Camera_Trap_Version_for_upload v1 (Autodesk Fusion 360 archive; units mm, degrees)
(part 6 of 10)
sketch "Sketch3" plane through (-24, 0, 0) normal (-1, 0, 0) x axis (0, -1, 0)
  line L1 (-33, 30) -> (-53, 30)
  line L2 (-2.8201, 30) -> (-33, 30)
  curve K1 (35.395, 253.2053) -> (39.3474, 235.851)
  line L3 (35.395, 254.9773) -> (35.395, 253.2053)
  line L4 (-53.3744, 254.9773) -> (35.395, 254.9773)
  line L5 (-53.3744, 30) -> (-53.3744, 254.9773)
  line L6 (-53, 30) -> (-53.3744, 30)
  line L7 (-35, 194) -> (-35, 213)
  line L8 (-42, 194) -> (-35, 194)
  line L9 (-42, 213) -> (-42, 194)
  line L10 (-35, 213) -> (-42, 213)
  line L11 (-46.1387, 104.755) -> (-18.6307, 104.755)
  line L12 (-49.1387, 175.7967) -> (-49.1387, 107.755)
  line L13 (-18.6307, 178.7967) -> (-46.1387, 178.7967)
  line L14 (-15.6307, 107.755) -> (-15.6307, 175.7967)
  curve K2 (-13.4543, 92.4987) -> (-13.7844, 52.0839)
  curve K3 (-13.7844, 52.0839) -> (10.3481, 52.6282)
  line L15 (23.9949, 221.9266) -> (23.9949, 191.9266)
  line L16 (-16.0051, 231.9266) -> (13.9949, 231.9266)
  line L17 (-26.0051, 191.9266) -> (-26.0051, 221.9266)
  line L18 (13.9949, 181.9266) -> (-16.0051, 181.9266)
  line L19 (9.6256, 120.7716) -> (-33.3744, 120.7716)
  line L20 (17.6256, 146.7716) -> (17.6256, 128.7716)
  line L21 (-33.3744, 154.7716) -> (9.6256, 154.7716)
  line L22 (-41.3744, 128.7716) -> (-41.3744, 146.7716)
  line L23 (35.0206, 254.9769) -> (-53.3744, 254.9769)
  curve K4 (35.0206, 254.9769) -> (38.973, 237.6226)
  line L24 (-3.1945, 31.7716) -> (-33.3744, 31.7716)
  line L25 (-33.3744, 31.7716) -> (-53.3744, 31.7716)
  line L26 (-53.3744, 31.7716) -> (-53.3744, 254.9769)
  curve K5 (21.1288, 76.5054) -> (12.4903, 90.2086)
  curve K6 (12.4903, 90.2086) -> (-13.4543, 92.4987)
  arc A1 centre (-2.8201, 80) radius 50 clockwise from (39.6517, 106.3845) to (-2.8201, 30)
  arc A2 centre (82.1236, 132.769) radius 50 clockwise from (39.6517, 106.3845) to (32.1399, 134.0465)
  arc A3 centre (1.7685, 134.8228) radius 30.3814 clockwise from (31.815, 139.3208) to (32.1399, 134.0465)
  arc A4 centre (81.264, 146.7234) radius 50 clockwise from (31.815, 139.3208) to (40.632, 175.8617)
  arc A5 centre (0, 205) radius 50 clockwise from (39.3474, 235.851) to (40.632, 175.8617)
  arc A6 centre (-46.1387, 107.755) radius 3 clockwise from (-46.1387, 104.755) to (-49.1387, 107.755)
  arc A7 centre (-46.1387, 175.7967) radius 3 clockwise from (-49.1387, 175.7967) to (-46.1387, 178.7967)
  arc A8 centre (-18.6307, 175.7967) radius 3 clockwise from (-18.6307, 178.7967) to (-15.6307, 175.7967)
  arc A9 centre (-18.6307, 107.755) radius 3 clockwise from (-15.6307, 107.755) to (-18.6307, 104.755)
  arc A10 centre (-1.0051, 72.1266) radius 22.5629 clockwise from (21.1288, 76.5054) to (10.3481, 52.6282)
  arc A11 centre (13.9949, 221.9266) radius 10 clockwise from (13.9949, 231.9266) to (23.9949, 221.9266)
  arc A12 centre (-16.0051, 221.9266) radius 10 clockwise from (-26.0051, 221.9266) to (-16.0051, 231.9266)
  arc A13 centre (-16.0051, 191.9266) radius 10 clockwise from (-16.0051, 181.9266) to (-26.0051, 191.9266)
  arc A14 centre (13.9949, 191.9266) radius 10 clockwise from (23.9949, 191.9266) to (13.9949, 181.9266)
  arc A15 centre (-33.3744, 128.7716) radius 8 clockwise from (-33.3744, 120.7716) to (-41.3744, 128.7716)
  arc A16 centre (9.6256, 128.7716) radius 8 clockwise from (17.6256, 128.7716) to (9.6256, 120.7716)
  arc A17 centre (9.6256, 146.7716) radius 8 clockwise from (9.6256, 154.7716) to (17.6256, 146.7716)
  arc A18 centre (-33.3744, 146.7716) radius 8 clockwise from (-41.3744, 146.7716) to (-33.3744, 154.7716)
  arc A19 centre (38.1035, 198.1502) radius 5.767 clockwise from (41.4518, 193.4548) to (34.7552, 193.4548)
  arc A20 centre (38.1035, 88.1502) radius 5.767 clockwise from (41.4518, 83.4548) to (34.7552, 83.4548)
  arc A21 centre (-0.3744, 206.7716) radius 50 clockwise from (38.973, 237.6226) to (40.2576, 177.6333)
  arc A22 centre (80.8896, 148.495) radius 50 clockwise from (31.4406, 141.0924) to (40.2576, 177.6333)
  arc A23 centre (1.3941, 136.5944) radius 30.3814 clockwise from (31.4406, 141.0924) to (31.7655, 135.8181)
  arc A24 centre (81.7492, 134.5406) radius 50 clockwise from (39.2774, 108.1561) to (31.7655, 135.8181)
  arc A25 centre (-3.1945, 81.7716) radius 50 clockwise from (39.2774, 108.1561) to (-3.1945, 31.7716)
sketch "Sketch1" plane through (0, 60, 0) normal (0, 1, 0) x axis (-1, 0, 0)
  line L1 (-132, 253.2053) -> (24, 253.2053)
  line L2 (-132, 28) -> (-132, 253.2053)
  line L3 (24, 28) -> (-132, 28)
  line L4 (24, 253.2053) -> (24, 28)
  line L5 (-54, 222.0559) -> (-54, 253.2053)
  circle C1 centre (-110, 230) radius 2.5
  circle C2 centre (-110, 50) radius 2.5
  circle C3 centre (2, 50) radius 2.5
  circle C4 centre (2, 230) radius 2.5
  point P6 (-54, 253.2053)
  midpoint L1 P6
  perpendicular L1 L5
  symmetric L5 C1 C4
  symmetric L5 C2 C3
  dimension "d1270" diameter C1 = 5
  dimension "d1271" diameter C2 = 5
extrude "Extrude1" cut sketch "Sketch1" profile of C1 C2 C3 C4 to an object
combine "Combine2"
sketch "Sketch2" plane through (-24, 0, 0) normal (-1, 0, 0) x axis (0, -1, 0)
  line L1 (-46.1387, 104.755) -> (-18.6307, 104.755)
  line L2 (-49.1387, 175.7967) -> (-49.1387, 107.755)
  line L3 (-18.6307, 178.7967) -> (-46.1387, 178.7967)
  line L4 (-15.6307, 107.755) -> (-15.6307, 175.7967)
  line L5 (-35, 194) -> (-35, 213)
  line L6 (-42, 194) -> (-35, 194)
  line L7 (-42, 213) -> (-42, 194)
  line L8 (-35, 213) -> (-42, 213)
  line L9 (-53, 30) -> (-53, 254.9308)
  line L10 (-33, 30) -> (-53, 30)
  line L11 (-2.8201, 30) -> (-33, 30)
  curve K1 (35.395, 253.2053) -> (39.3474, 235.851)
  line L12 (2.6295, 254.9308) -> (35.395, 253.2053)
  line L13 (-53, 254.9308) -> (-2.6295, 254.9308)
  line L14 (-53, 253.2053) -> (35.395, 253.2053)
  line L15 (35.395, 254.9308) -> (-53, 254.9308)
  line L16 (35.395, 253.2053) -> (35.395, 254.9308)
  arc A1 centre (-46.1387, 107.755) radius 3 clockwise from (-46.1387, 104.755) to (-49.1387, 107.755)
  arc A2 centre (-46.1387, 175.7967) radius 3 clockwise from (-49.1387, 175.7967) to (-46.1387, 178.7967)
  arc A3 centre (-18.6307, 175.7967) radius 3 clockwise from (-18.6307, 178.7967) to (-15.6307, 175.7967)
  arc A4 centre (-18.6307, 107.755) radius 3 clockwise from (-15.6307, 107.755) to (-18.6307, 104.755)
  arc A5 centre (-2.8201, 80) radius 50 clockwise from (39.6517, 106.3845) to (-2.8201, 30)
  arc A6 centre (82.1236, 132.769) radius 50 clockwise from (39.6517, 106.3845) to (32.1399, 134.0465)
  arc A7 centre (1.7685, 134.8228) radius 30.3814 clockwise from (31.815, 139.3208) to (32.1399, 134.0465)
  arc A8 centre (81.264, 146.7234) radius 50 clockwise from (31.815, 139.3208) to (40.632, 175.8617)
  arc A9 centre (0, 205) radius 50 clockwise from (39.3474, 235.851) to (40.632, 175.8617)
  arc A10 centre (0, 205) radius 50 clockwise from (-2.6295, 254.9308) to (2.6295, 254.9308)
  point P32 (35.395, 253.2053)
  point P35 (35.395, 253.2053)
  point P36 (-53, 253.2053)
  point P18 (-53, 254.9308)
  point P37 (-53, 254.9308)
  point P39 (35.395, 253.2053)
  coincident P32 P35
  coincident L9 P36
  perpendicular L9 L14
  coincident P18 P37
  perpendicular L9 L15
  coincident P32 P39
  vertical L16
extrude "Extrude2" cut sketch "Sketch2" profile of L9 L12 L13 L14 L15 against normal blind 7
extrude "Extrude3" cut of existing geometry blind -7
extrude "Extrude2" cut of existing geometry to an object
offset_faces "OffsetFaces2" distance 2
extrude "Extrude79" new body of existing geometry to an object
remove_instance "RemoveInstance1"
remove_instance "RemoveInstance2"
remove_instance "RemoveInstance3"
remove_instance "RemoveInstance4"
remove_instance "RemoveInstance5"
remove_instance "RemoveInstance15"
remove_instance "RemoveInstance16"
remove_instance "RemoveInstance6"
sketch "Sketch1" plane through (132.1975, 0, 0) normal (1, 0, 0) x axis (0, 1, 0)
  circle C1 centre (0.6307, 70.355) radius 4.1
  circle C2 centre (0.6307, 70.355) radius 11
  circle C3 centre (0.6307, 70.355) radius 11.1
  circle C4 centre (0.6307, 70.355) radius 13
  circle C5 centre (0.6307, 70.355) radius 6.5
  circle C6 centre (0.6307, 70.355) radius 32.5
  concentric C1 C3
  concentric C3 C4
  concentric C3 C5
  concentric C3 C6
  dimension "d1284" diameter C3 = 22.2
  dimension "d1285" diameter C4 = 26
  dimension "d1286" diameter C5 = 13
  dimension "d1294" diameter C6 = 65
extrude "Extrude2" new body sketch "Sketch1" profile of C3 C4 against normal blind 7
extrude "Extrude3" new body sketch "Sketch1" profile of C2 C3 C4 C5 along normal blind 1
extrude "Extrude4" add sketch "Sketch1" profile of C1 C2 C3 C4 C5 blind 2 from offset 1
combine "Combine3"
extrude "Extrude5" add sketch "Sketch1" profile of C4 C6 against normal blind 7 and against normal blind 0
extrude "Extrude6" new body sketch "Sketch1" along normal blind 2
base_feature "Base Feature1" bodies "interior_motor_holder", "interior_motor_holder_alternative"
offset_faces "OffsetFaces1" distance -1 named "d1237_1"
offset_faces "OffsetFaces2" distance -1 named "d1238_1"
position "Position32"
sketch "Sketch1" plane through (61.25, 0, 0) normal (1, 0, 0) x axis (0, 1, 0)
  line L1 (50, 114.9665) -> (27.8, 114.9665)
  line L2 (50, 151.0335) -> (50, 114.9665)
  line L3 (27.8, 151.0335) -> (50, 151.0335)
  line L4 (6.9663, 163) -> (13.1099, 163)
  line L5 (6.8934, 149.8497) -> (6.9663, 163)
  line L6 (6.9663, 103) -> (6.8934, 116.1503)
  line L7 (13.1099, 103) -> (6.9663, 103)
  line L8 (35, 204) -> (35, 195.1585)
  line L9 (41, 195.1585) -> (41, 204)
  line L10 (35, 119.0366) -> (35, 170.1585)
  line L11 (41, 170.1585) -> (41, 119.0366)
  line L12 (41, 119.0366) -> (41, 110.9415)
  line L13 (35, 119.0366) -> (35, 110.9415)
  line L14 (41, 170.1585) -> (41, 175.1585)
  line L15 (41, 195.1585) -> (41, 175.1585)
  line L16 (41, 207.6585) -> (41, 204)
  line L17 (41, 207.6585) -> (41, 210.1585)
  line L18 (41, 105.9415) -> (41, 110.9415)
  line L19 (35, 210.1585) -> (35, 207.6585)
  line L20 (41, 210.1585) -> (35, 210.1585)
  line L21 (35, 175.1585) -> (35, 170.1585)
  line L22 (35, 110.9415) -> (35, 105.9415)
  line L23 (35, 105.9415) -> (41, 105.9415)
  line L24 (35, 207.6585) -> (35, 204)
  line L25 (35, 195.1585) -> (35, 175.1585)
  line L26 (32, 151.0335) -> (35, 151.0335)
  line L27 (32, 156.0335) -> (32, 151.0335)
  line L28 (35, 156.0335) -> (32, 156.0335)
  line L29 (35, 151.0335) -> (35, 156.0335)
  line L30 (32, 114.9891) -> (35, 114.9891)
  line L31 (32, 109.9891) -> (32, 114.9891)
  line L32 (35, 109.9891) -> (32, 109.9891)
  line L33 (35, 114.9891) -> (35, 109.9891)
  arc A1 centre (13.1099, 106) radius 3 clockwise from (16.048, 105.3933) to (13.1099, 103)
  arc A2 centre (27.8, 102.9665) radius 12 clockwise from (16.048, 105.3933) to (27.8, 114.9665)
  arc A3 centre (27.8, 163.0335) radius 12 clockwise from (27.8, 151.0335) to (16.048, 160.6067)
  arc A4 centre (13.1099, 160) radius 3 clockwise from (13.1099, 163) to (16.048, 160.6067)
  arc A5 centre (6.8, 133) radius 16.85 clockwise from (6.8934, 149.8497) to (6.8934, 116.1503)
  point P37 (35, 151.0335)
  point P41 (35, 114.9891)
  point P38 (32, 151.0335)
  point P40 (35, 156.0335)
  point P42 (32, 114.9891)
  point P44 (35, 109.9891)
  horizontal L26
  vertical L27
  horizontal L28
  vertical L29
  coincident L3 P37
  coincident L10 P37
  horizontal L30
  vertical L31
  horizontal L32
  vertical L33
  midpoint L13 P41
  dimension "d1301" distance P37 P38 = 3
  dimension "d1302" distance P37 P40 = 5
  dimension "d1303" distance P41 P42 = 3
  dimension "d1304" distance P41 P44 = 5
extrude "Extrude1" add sketch "Sketch1" profile of L1 L3 L10 L13 L22 L26 L27 L28 L29 L31 L32 L33 against normal blind 10
fillet "Fillet1" radius 5
fillet "Fillet2" radius 5
extrude "Extrude2" add of existing geometry blind 4
extrude "Extrude3" add of existing geometry blind 4
sketch "Sketch2" plane through (0, 35, 0) normal (0, 1, 0) x axis (-1, 0, 0)
  line L1 (-61.25, 151.0335) -> (-61.25, 160.0335)
  line L2 (-51.25, 151.0335) -> (-61.25, 151.0335)
  line L3 (-51.25, 160.0335) -> (-51.25, 151.0335)
  line L4 (-61.25, 160.0335) -> (-51.25, 160.0335)
  line L5 (-80, 133) -> (-27, 133)
  circle C1 centre (-56, 156.5) radius 1.25
  circle C2 centre (-56, 109.5) radius 1.25
  horizontal L5
  symmetric L5 C1 C2
  dimension "d1315" diameter C1 = 2.5
extrude "Extrude4" cut sketch "Sketch2" profile of C1 C2 against normal blind 3.2
extrude "Extrude3" add of existing geometry to an object
extrude "Extrude7" add of existing geometry blind 4
extrude "Extrude8" new body sketch "Sketch1" profile of C4 C6 against normal blind 6 bodies "Coil"
extrude "Extrude10" cut sketch "Sketch1" profile of C1 C5 along normal blind 1
extrude "Extrude11" add of existing geometry blind 10
position "Position33"
extrude "Extrude4" cut of existing geometry blind -0.376
sketch "Sketch6" plane through (128.8025, 0, 0) normal (-1, 0, 0) x axis (0, -1, 0)
  curve K1 (35.8734, 253.4503) -> (39.8258, 236.096)
  line L1 (-52.5216, 253.4503) -> (35.8734, 253.4503)
  line L2 (-52.5216, 28.245) -> (-52.5216, 253.4503)
  line L3 (-32.5216, 28.245) -> (-52.5216, 28.245)
  line L4 (-2.3417, 28.245) -> (-32.5216, 28.245)
  line L5 (-32.5216, 113.6781) -> (10.4784, 113.6781)
  line L6 (-40.5216, 127.245) -> (-46.0885, 127.245)
  line L7 (-40.5216, 135.245) -> (-40.5216, 127.245)
  line L8 (-46.0885, 135.245) -> (-40.5216, 135.245)
  line L9 (-46.0885, 145.245) -> (-46.0885, 135.245)
  line L10 (10.4784, 158.8119) -> (-32.5216, 158.8119)
  line L11 (24.0453, 127.245) -> (24.0453, 145.245)
  curve K2 (13.3431, 88.682) -> (-24.7719, 73.9853)
  curve K3 (-18.2149, 53.5317) -> (21.3407, 63.7345)
  line L12 (24.8477, 190.4) -> (24.8477, 220.4)
  line L13 (-15.1523, 180.4) -> (14.8477, 180.4)
  line L14 (-25.1523, 220.4) -> (-25.1523, 190.4)
  line L15 (14.8477, 230.4) -> (-15.1523, 230.4)
  curve K4 (35.608, 201.319) -> (35.968, 190.392)
  curve K5 (41.9446, 190.392) -> (42.3046, 201.319)
  curve K6 (35.608, 91.319) -> (35.968, 80.392)
  curve K7 (41.9446, 80.392) -> (42.3046, 91.319)
  line L16 (-32.3693, 28.245) -> (-2.1894, 28.245)
  line L17 (-52.3693, 28.245) -> (-32.3693, 28.245)
  line L18 (-52.3693, 253.4503) -> (-52.3693, 28.245)
  line L19 (36.0257, 253.4503) -> (-52.3693, 253.4503)
  curve K8 (36.0257, 253.4503) -> (39.9781, 236.096)
  line L20 (-12.7796, 133.0972) -> (-12.7796, 143.0972)
  line L21 (12.6204, 143.0972) -> (12.6204, 133.0972)
  line L22 (-34.3693, 213.245) -> (-34.3693, 194.245)
  line L23 (-41.3693, 213.245) -> (-34.3693, 213.245)
  line L24 (-41.3693, 194.245) -> (-41.3693, 213.245)
  line L25 (-34.3693, 194.245) -> (-41.3693, 194.245)
  line L26 (0.6307, 205.245) -> (-0.0736, 205.414)
  arc A1 centre (2.2469, 135.0677) radius 30.3814 clockwise from (32.2934, 139.5658) to (32.622, 135.6838)
  arc A2 centre (81.7424, 146.9684) radius 50 clockwise from (32.2934, 139.5658) to (41.1104, 176.1067)
  arc A3 centre (0.4784, 205.245) radius 50 clockwise from (39.8258, 236.096) to (41.1104, 176.1067)
  arc A4 centre (-2.3417, 80.245) radius 52 clockwise from (40.9679, 109.0248) to (-2.3417, 28.245)
  arc A5 centre (82.6117, 136.6977) radius 50 clockwise from (40.9679, 109.0248) to (32.622, 135.6838)
  arc A6 centre (10.4784, 127.245) radius 13.5669 clockwise from (24.0453, 127.245) to (10.4784, 113.6781)
  arc A7 centre (-32.5216, 127.245) radius 13.5669 clockwise from (-32.5216, 113.6781) to (-46.0885, 127.245)
  arc A8 centre (-32.5216, 145.245) radius 13.5669 clockwise from (-46.0885, 145.245) to (-32.5216, 158.8119)
  arc A9 centre (10.4784, 145.245) radius 13.5669 clockwise from (10.4784, 158.8119) to (24.0453, 145.245)
  arc A10 centre (-0.1523, 70.6) radius 22.5629 clockwise from (13.3431, 88.682) to (21.3407, 63.7345)
  arc A11 centre (-0.1523, 70.6) radius 24.8513 clockwise from (-18.2149, 53.5317) to (-24.7719, 73.9853)
  arc A12 centre (14.8477, 190.4) radius 10 clockwise from (24.8477, 190.4) to (14.8477, 180.4)
  arc A13 centre (-15.1523, 190.4) radius 10 clockwise from (-15.1523, 180.4) to (-25.1523, 190.4)
  arc A14 centre (-15.1523, 220.4) radius 10 clockwise from (-25.1523, 220.4) to (-15.1523, 230.4)
  arc A15 centre (14.8477, 220.4) radius 10 clockwise from (14.8477, 230.4) to (24.8477, 220.4)
  arc A16 centre (38.9563, 196.6236) radius 5.767 clockwise from (35.608, 201.319) to (42.3046, 201.319)
  arc A17 centre (38.9563, 196.6236) radius 6.911 clockwise from (41.9446, 190.392) to (35.968, 190.392)
  arc A18 centre (38.9563, 86.6236) radius 5.767 clockwise from (35.608, 91.319) to (42.3046, 91.319)
  arc A19 centre (38.9563, 86.6236) radius 6.911 clockwise from (41.9446, 80.392) to (35.968, 80.392)
  arc A20 centre (-2.1894, 80.245) radius 52 clockwise from (41.1202, 109.0248) to (-2.1894, 28.245)
  arc A21 centre (0.6307, 205.245) radius 50 clockwise from (39.9781, 236.096) to (41.2627, 176.1067)
  arc A22 centre (81.8947, 146.9684) radius 50 clockwise from (32.4457, 139.5658) to (41.2627, 176.1067)
  arc A23 centre (2.3992, 135.0677) radius 30.3814 clockwise from (32.4457, 139.5658) to (32.7743, 135.6838)
  arc A24 centre (82.764, 136.6977) radius 50 clockwise from (41.1202, 109.0248) to (32.7743, 135.6838)
  circle C1 centre (-50.3693, 205.245) radius 1.5
  circle C2 centre (0, 70.6) radius 13.1
  arc A25 centre (-0.0796, 133.0972) radius 12.7 clockwise from (12.6204, 133.0972) to (-12.7796, 133.0972)
  arc A26 centre (-0.0796, 143.0972) radius 12.7 clockwise from (-12.7796, 143.0972) to (12.6204, 143.0972)
  circle C3 centre (-0.0736, 205.414) radius 13.1
  circle C4 centre (39.1086, 86.6236) radius 7
  circle C5 centre (39.1086, 196.6236) radius 7
  circle C6 centre (39.1086, 86.6236) radius 7
  circle C7 centre (39.1086, 86.6236) radius 7
  point P82 (-0.0736, 205.414)
  point P89 (-0.0736, 205.414)
  point P68 (0.6307, 205.245)
  point P90 (0.6307, 205.245)
  coincident P82 P89
  coincident P68 P90
extrude "Extrude12" add of existing geometry blind 0.3
position "Position34"
sketch "Sketch3" plane through (125, 0, 0) normal (-1, 0, 0) x axis (0, -1, 0)
  curve K1 (35.1296, 91.074) -> (35.4896, 80.147)
  curve K2 (41.4661, 80.147) -> (41.8261, 91.074)
  curve K3 (35.1296, 201.074) -> (35.4896, 190.147)
  curve K4 (41.4661, 190.147) -> (41.8261, 201.074)
  line L1 (24.3693, 190.155) -> (24.3693, 220.155)
  line L2 (-15.6307, 180.155) -> (14.3693, 180.155)
  line L3 (-25.6307, 220.155) -> (-25.6307, 190.155)
  line L4 (14.3693, 230.155) -> (-15.6307, 230.155)
  curve K5 (17.7406, 83.4539) -> (-23.0415, 81.0947)
  curve K6 (-18.6933, 53.2867) -> (20.8623, 63.4895)
  line L5 (-33, 113.4331) -> (10, 113.4331)
  line L6 (-41, 127) -> (-46.5669, 127)
  line L7 (-41, 135) -> (-41, 127)
  line L8 (-46.5669, 135) -> (-41, 135)
  line L9 (-46.5669, 145) -> (-46.5669, 135)
  line L10 (10, 158.5669) -> (-33, 158.5669)
  line L11 (23.5669, 127) -> (23.5669, 145)
  curve K7 (35.395, 253.2053) -> (39.3474, 235.851)
  line L12 (-53, 253.2053) -> (35.395, 253.2053)
  line L13 (-53, 28) -> (-53, 253.2053)
  line L14 (-33, 28) -> (-53, 28)
  line L15 (-2.8201, 28) -> (-33, 28)
  arc A1 centre (38.4779, 86.3786) radius 5.767 clockwise from (35.1296, 91.074) to (41.8261, 91.074)
  arc A2 centre (38.4779, 86.3786) radius 6.911 clockwise from (41.4661, 80.147) to (35.4896, 80.147)
  arc A3 centre (38.4779, 196.3786) radius 5.767 clockwise from (35.1296, 201.074) to (41.8261, 201.074)
  arc A4 centre (38.4779, 196.3786) radius 6.911 clockwise from (41.4661, 190.147) to (35.4896, 190.147)
  arc A5 centre (14.3693, 190.155) radius 10 clockwise from (24.3693, 190.155) to (14.3693, 180.155)
  arc A6 centre (-15.6307, 190.155) radius 10 clockwise from (-15.6307, 180.155) to (-25.6307, 190.155)
  arc A7 centre (-15.6307, 220.155) radius 10 clockwise from (-25.6307, 220.155) to (-15.6307, 230.155)
  arc A8 centre (14.3693, 220.155) radius 10 clockwise from (14.3693, 230.155) to (24.3693, 220.155)
  arc A9 centre (-0.6307, 70.355) radius 24.8512 clockwise from (-23.0417, 59.6158) to (-23.0415, 81.0947)
  arc A10 centre (-0.6307, 70.355) radius 22.5629 clockwise from (17.7406, 83.4539) to (20.8623, 63.4895)
  arc A11 centre (-0.6307, 70.355) radius 24.8512 clockwise from (-18.6933, 53.2867) to (-23.0417, 59.6158)
  arc A12 centre (10, 127) radius 13.5669 clockwise from (23.5669, 127) to (10, 113.4331)
  arc A13 centre (-33, 127) radius 13.5669 clockwise from (-33, 113.4331) to (-46.5669, 127)
  arc A14 centre (-33, 145) radius 13.5669 clockwise from (-46.5669, 145) to (-33, 158.5669)
  arc A15 centre (10, 145) radius 13.5669 clockwise from (10, 158.5669) to (23.5669, 145)
  arc A16 centre (1.7685, 134.8228) radius 30.3814 clockwise from (31.815, 139.3208) to (32.1436, 135.4388)
  arc A17 centre (81.264, 146.7234) radius 50 clockwise from (31.815, 139.3208) to (40.632, 175.8617)
  arc A18 centre (0, 205) radius 50 clockwise from (39.3474, 235.851) to (40.632, 175.8617)
  arc A19 centre (-2.8201, 80) radius 52 clockwise from (40.4895, 108.7798) to (-2.8201, 28)
  arc A20 centre (82.1333, 136.4527) radius 50 clockwise from (40.4895, 108.7798) to (32.1436, 135.4388)
  circle C1 centre (38.4779, 86.3786) radius 8.0139
  circle C2 centre (38.4779, 196.3786) radius 10.6505
  concentric A1 C1
  concentric A3 C2
extrude "Extrude13" add sketch "Sketch3" profile of K1 A1 K2 A2 K3 A3 K4 A4 A18 C1 C2 against normal blind 7
sketch "Sketch4" plane through (125, 0, 0) normal (-1, 0, 0) x axis (0, -1, 0)
  curve K1 (35.395, 253.2053) -> (39.3474, 235.851)
  line L1 (-53, 253.2053) -> (35.395, 253.2053)
  line L2 (-53, 28) -> (-53, 253.2053)
  line L3 (-33, 28) -> (-53, 28)
  line L4 (-2.8201, 28) -> (-33, 28)
  line L5 (-33, 113.4331) -> (10, 113.4331)
  line L6 (-41, 127) -> (-46.5669, 127)
  line L7 (-41, 135) -> (-41, 127)
  line L8 (-46.5669, 135) -> (-41, 135)
  line L9 (-46.5669, 145) -> (-46.5669, 135)
  line L10 (10, 158.5669) -> (-33, 158.5669)
  line L11 (23.5669, 127) -> (23.5669, 145)
  curve K2 (17.7406, 83.4539) -> (-23.0415, 81.0947)
  curve K3 (-18.6933, 53.2867) -> (20.8623, 63.4895)
  line L12 (24.3693, 190.155) -> (24.3693, 220.155)
  line L13 (-15.6307, 180.155) -> (14.3693, 180.155)
  line L14 (-25.6307, 220.155) -> (-25.6307, 190.155)
  line L15 (14.3693, 230.155) -> (-15.6307, 230.155)
  arc A1 centre (0, 205) radius 50 clockwise from (39.3474, 235.851) to (40.632, 175.8617)
  arc A2 centre (-2.8201, 80) radius 52 clockwise from (40.4895, 108.7798) to (-2.8201, 28)
  arc A3 centre (82.1333, 136.4527) radius 50 clockwise from (40.4895, 108.7798) to (32.1436, 135.4388)
  arc A4 centre (1.7685, 134.8228) radius 30.3814 clockwise from (31.815, 139.3208) to (32.1436, 135.4388)
  arc A5 centre (81.264, 146.7234) radius 50 clockwise from (31.815, 139.3208) to (40.632, 175.8617)
  arc A6 centre (10, 127) radius 13.5669 clockwise from (23.5669, 127) to (10, 113.4331)
  arc A7 centre (-33, 127) radius 13.5669 clockwise from (-33, 113.4331) to (-46.5669, 127)
  arc A8 centre (-33, 145) radius 13.5669 clockwise from (-46.5669, 145) to (-33, 158.5669)
  arc A9 centre (10, 145) radius 13.5669 clockwise from (10, 158.5669) to (23.5669, 145)
  arc A10 centre (-0.6307, 70.355) radius 24.8512 clockwise from (-23.0417, 59.6158) to (-23.0415, 81.0947)
  arc A11 centre (-0.6307, 70.355) radius 22.5629 clockwise from (17.7406, 83.4539) to (20.8623, 63.4895)
  arc A12 centre (-0.6307, 70.355) radius 24.8512 clockwise from (-18.6933, 53.2867) to (-23.0417, 59.6158)
  arc A13 centre (14.3693, 190.155) radius 10 clockwise from (24.3693, 190.155) to (14.3693, 180.155)
  arc A14 centre (-15.6307, 190.155) radius 10 clockwise from (-15.6307, 180.155) to (-25.6307, 190.155)
  arc A15 centre (-15.6307, 220.155) radius 10 clockwise from (-25.6307, 220.155) to (-15.6307, 230.155)
  arc A16 centre (14.3693, 220.155) radius 10 clockwise from (14.3693, 230.155) to (24.3693, 220.155)
  circle C1 centre (38.7498, 196.5785) radius 7
  circle C2 centre (38.7498, 86.5785) radius 7
  circle C3 centre (38.7498, 196.5785) radius 7
  circle C4 centre (38.7498, 86.5785) radius 7
  circle C5 centre (38.7498, 196.5785) radius 5.2
  circle C6 centre (38.7498, 86.5785) radius 5.2
  concentric C1 C3
  concentric C2 C4
  concentric C1 C5
  concentric C4 C6
  dimension "d1346" diameter C5 = 10.4
  dimension "d1347" diameter C6 = 10.4
extrude "Extrude1" new body sketch "Sketch4" profile of C1 C2 C3 C4 C5 C6 against normal blind 7
sketch "Sketch7" plane through (0, 0, 0) normal (0, 0, 1) x axis (1, 0, 0)
  circle C1 centre (150, 200) radius 7
  circle C2 centre (150, 200) radius 5.075
  circle C3 centre (150, 200) radius 3.5
  circle C4 centre (175, 210) radius 6.9
  circle C5 centre (175, 210) radius 5.075
  concentric C1 C2
  concentric C2 C3
  concentric C4 C5
  dimension "d1366" diameter C1 = 14
  dimension "d1367" diameter C2 = 10.15
  dimension "d1376" diameter C3 = 7
  dimension "d1380" diameter C4 = 13.8
  dimension "d1381" diameter C5 = 10.15
extrude "Extrude29" new body sketch "Sketch7" profile of C1 C2 along normal blind 4 bodies "Screw (1)"
extrude "Extrude30" new body sketch "Sketch7" profile of C1 C2 blind 2 from offset 4
extrude "Extrude31" new body sketch "Sketch7" profile of C1 C2 blind 11 from offset 6
thread "Thread1" ThreadOffset 0 ThreadLength 10
combine "Combine7"
offset_faces "OffsetFaces1" distance -0.2
extrude "Extrude32" new body sketch "Sketch7" profile of C4 C5 along normal blind 4 bodies "Cap"
extrude "Extrude33" add sketch "Sketch7" profile of C5 along normal blind 1
thread "Thread3" ThreadOffset 0 ThreadLength 10
thread "Thread4" ThreadOffset 0 ThreadLength 10
combine "Combine11"
work_plane "WorkPlane1" AlongDistance -7 named "d454_1"
sketch "Sketch2" plane through (-7, 0, 0) normal (-1, 0, 0) x axis (0, -1, 0)
  line L1 (0, 70.6) -> (0, 0)
  circle C1 centre (0, 70.6) radius 11.1
  circle C2 centre (0, 70.6) radius 13.1
  circle C3 centre (0, 70.6) radius 6.5
  point P1 (0, 0)
  point P2 (0, 0)
  point P3 (0, 70.6)
  point P4 (0, 70.6)
  coincident P1 P2
  vertical L1
  coincident P3 P4
  concentric C1 C2
  concentric C2 C3
  dimension "d469_1" distance P2 P3 = 70.6
  dimension "d470_1" diameter C1 = 22.2
  dimension "d471_1" diameter C2 = 26.2
  dimension "d472_1" diameter C3 = 13
extrude "Extrude3" new body sketch "Sketch2" profile of C1 C2 along normal blind 7 named "d473_1" bodies "Left_Wall_Cap_Low"
extrude "Extrude4" new body sketch "Sketch2" profile of C1 C2 C3 blind 2 named "d476_1" from offset 7 named "d475_1"
extrude "Extrude5" cut sketch "Sketch2" profile of C3 blind 1 named "d479_1" from offset 7 named "d478_1"
combine "Combine1"
copy_paste_bodies "CopyPasteBodies1"
move "Move1" TranslateX 0 named "d481_1" TranslateY 0 named "d482_1" TranslateZ 62.6 named "d483_1"
sketch "Sketch4" plane through (-16, 0, 0) normal (-1, 0, 0) x axis (0, -1, 0)
  line L1 (15, 100.6) -> (-15, 100.6)
  line L2 (-30, 85.6) -> (-30, 55.6)
  line L3 (-15, 40.6) -> (15, 40.6)
  line L4 (30, 55.6) -> (30, 85.6)
  line L5 (-50, 215.4) -> (-50, 210.501)
  line L6 (0, 210.4) -> (-45, 210.4)
  line L7 (-45, 180.4) -> (0, 180.4)
  line L8 (-50, 180.299) -> (-50, 175.4)
  line L9 (-50, 210.501) -> (-50, 180.299)
  line L10 (-50, 152.0335) -> (-50, 113.9665)
  line L11 (-27.8, 152.0335) -> (-50, 152.0335)
  line L12 (-6.9663, 163) -> (-14.1326, 163)
  line L13 (-6.8934, 149.8497) -> (-6.9663, 163)
  line L14 (-6.9663, 103) -> (-6.8934, 116.1503)
  line L15 (-14.1326, 103) -> (-6.9663, 103)
  line L16 (-50, 113.9665) -> (-27.8, 113.9665)
  line L17 (-50, 0) -> (-50, 250)
  line L18 (50, 0) -> (-50, 0)
  line L19 (0, 219.4) -> (0, 215.4)
  line L20 (30, 40.6) -> (-50, 40.6)
  line L21 (50, 40.6) -> (-50, 40.6)
  line L22 (50, 170.6) -> (50, 60.6)
  line L23 (-50, 170.6) -> (50, 170.6)
  line L24 (-50, 40.6) -> (-50, 170.6)
  circle C1 centre (0, 70.6) radius 13.1
  circle C2 centre (-27.5, 70.6) radius 1
  circle C3 centre (27.5, 70.6) radius 1
  circle C4 centre (0, 43.1) radius 1
  circle C5 centre (0, 98.1) radius 1
  arc A1 centre (-15, 85.6) radius 15 clockwise from (-30, 85.6) to (-15, 100.6)
  arc A2 centre (-15, 55.6) radius 15 clockwise from (-15, 40.6) to (-30, 55.6)
  arc A3 centre (15, 55.6) radius 15 clockwise from (30, 55.6) to (15, 40.6)
  arc A4 centre (15, 85.6) radius 15 clockwise from (15, 100.6) to (30, 85.6)
  arc A5 centre (-45, 215.4) radius 5 clockwise from (-45, 210.4) to (-50, 215.4)
  arc A6 centre (0, 195.4) radius 15 clockwise from (0, 210.4) to (0, 180.4)
  arc A7 centre (-45, 175.4) radius 5 clockwise from (-50, 175.4) to (-45, 180.4)
  circle C6 centre (0, 195.4) radius 6.5
  arc A8 centre (-27.8, 163.0335) radius 11 clockwise from (-17.0613, 160.65) to (-27.8, 152.0335)
  arc A9 centre (-14.1326, 160) radius 3 clockwise from (-17.0613, 160.65) to (-14.1326, 163)
  arc A10 centre (-6.8, 133) radius 16.85 clockwise from (-6.8934, 116.1503) to (-6.8934, 149.8497)
  arc A11 centre (-14.1326, 106) radius 3 clockwise from (-14.1326, 103) to (-17.0613, 105.35)
  arc A12 centre (-27.8, 102.9665) radius 11 clockwise from (-27.8, 113.9665) to (-17.0613, 105.35)
  circle C7 centre (0, 195.4) radius 20
  arc A13 centre (30, 60.6) radius 20 clockwise from (50, 60.6) to (30, 40.6)
  circle C8 centre (0, 133.2) radius 13.1
  circle C9 centre (0, 70.6) radius 13.1
  point P51 (0, 215.4)
  point P53 (-50, 40.6)
  point P54 (50, 40.6)
  point P49 (-50, 0)
  point P50 (50, 0)
  point P52 (0, 219.4)
  point P56 (-50, 170.6)
  parallel L10 L17
  perpendicular L17 L18
  coincident C7 P51
  perpendicular L6 L19
  coincident L17 P53
  perpendicular L17 L20
  horizontal L21
  vertical L22
  horizontal L23
  vertical L24
  coincident P54 L22
  tangent L22 A13
  tangent L20 A13
  dimension "d487_1" distance P49 P50 = 100
  dimension "d488_1" distance P51 P52 = 4
  dimension "d489_1" distance P53 P54 = 100
  dimension "d490_1" distance P53 P56 = 130
  dimension "d491_1" radius A13 = 20
extrude "Extrude6" new body sketch "Sketch4" profile of C1 C2 C3 C4 C5 L1 A1 L2 A2 L3 A3 L4 A4 L10 L11 A8 A9 L12 L13 A10 L14 L15 A11 A12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 along normal blind 5 named "d496_1" and against normal blind 3 named "d498_1" bodies "Extrusion_Wall"
extrude "Extrude7" new body sketch "Sketch4" profile of C1 C8 C9 along normal blind 5 named "d500_1" bodies "Extrusion_hole Mid", "Extrusion_hold_Upper"
combine "Combine3"
sketch "Sketch5" plane through (0, -50, 0) normal (0, -1, 0) x axis (1, 0, 0)
  line L1 (-21, 170.6) -> (-13, 170.6)
  line L2 (-21, 60.6) -> (-21, 170.6)
  line L3 (-13, 60.6) -> (-21, 60.6)
  line L4 (-13, 170.6) -> (-13, 60.6)
  line L5 (-15, 199.4075) -> (-15, 191.3925)
  curve K1 (-15, 191.3925) -> (-13.5, 191.3)
  curve K2 (-13.5, 199.5) -> (-15, 199.4075)
  line L6 (5, 192.4087) -> (5, 199.5)
  line L7 (0, 192.4087) -> (5, 192.4087)
  line L8 (0, 199.5) -> (0, 200.4)
  line L9 (0, 190.4) -> (0, 192.4087)
  line L10 (-2, 199.5) -> (-2, 200.4)
  line L11 (-2, 190.4) -> (-2, 191.3)
  line L12 (-13.5, 199.5) -> (-2, 199.5)
  line L13 (-13.5, 191.3) -> (-2, 191.3)
  line L14 (-2, 200.4) -> (0, 200.4)
  line L15 (-2, 190.4) -> (0, 190.4)
  line L16 (0, 199.5) -> (5, 199.5)
  line L17 (-18, 199.4075) -> (-15, 199.4075)
  line L18 (-27, 170.6063) -> (-13, 170.6063)
  line L19 (-32, 215) -> (-32, 175.6063)
  line L20 (-34, 163.6063) -> (-13, 163.6063)
  line L21 (-39, 215) -> (-39, 168.6063)
  line L22 (-13, 163.6063) -> (-13, 170.6063)
  line L23 (-32, 215) -> (-39, 215)
  line L24 (-13, 163.6063) -> (-13, 170.6063)
  arc A1 centre (-34, 168.6063) radius 5 clockwise from (-34, 163.6063) to (-39, 168.6063)
  arc A2 centre (-27, 175.6063) radius 5 clockwise from (-27, 170.6063) to (-32, 175.6063)
  point P7 (-15, 199.4075)
  point P20 (-15, 199.4075)
  point P22 (-13, 170.6063)
  point P21 (-18, 199.4075)
  coincident P7 P20
  perpendicular L5 L17
  coincident L4 P22
  perpendicular L4 L18
  perpendicular L18 L19
  tangent L20 A1
  tangent L21 A1
  perpendicular L20 L22
  tangent L19 A2
  tangent L18 A2
  perpendicular L19 L23
  dimension "d502_1" distance P20 P21 = 3
  dimension "d504_1" radius A1 = 5
  dimension "d505_1" radius A2 = 5
extrude "Extrude8" add sketch "Sketch5" profile of L1 L2 L18 L19 L20 L21 A1 A2 L23 L24 against normal blind 100 named "d506_1"
copy_paste_bodies "CopyPasteBodies2"
move "Move2"
move "Move3"
move "Move4"
sketch "Sketch6" plane through (-5, 0, 0) normal (1, 0, 0) x axis (0, 1, 0)
  circle C1 centre (0, 70.6) radius 4.1
  circle C2 centre (0, 70.6) radius 13
  circle C3 centre (0, 70.6) radius 17.5
  circle C4 centre (0, 70.6) radius 6.5
  circle C5 centre (0, 70.6) radius 16
  concentric C1 C3
  concentric C3 C4
  concentric C4 C5
  dimension "d584_1" diameter C3 = 35
  dimension "d585_1" diameter C4 = 13
  dimension "d589_1" diameter C5 = 32
extrude "Extrude9" new body sketch "Sketch6" profile of C2 C3 C4 blind 2 named "d586_1" from offset 1 named "d588_1" bodies "Restraining_Cap"
extrude "Extrude10" add sketch "Sketch6" profile of C3 C5 blind -14 named "d591_1" from offset 2 named "d590_1"
move "Move5"
move "Move6"
move "Move7"
move "Move8"
move "Move9"
move "Move10"
move "Move11"
sketch "Sketch9" plane through (0, 0, 0) normal (1, 0, 0) x axis (0, 1, 0)
sketch "Test_Wall" plane through (-19, 0, 0) normal (-1, 0, 0) x axis (0, -1, 0)
  line L1 (-51, 105.9415) -> (-41, 105.9415)
  line L2 (-41, 170.1585) -> (-41, 105.9415)
  line L3 (-51, 105.9415) -> (-51, 170.1585)
  line L4 (-51, 170.1585) -> (-41, 170.1585)
  line L5 (25, 225) -> (-25, 225)
  line L6 (25, 50) -> (25, 225)
  line L7 (-25, 50) -> (25, 50)
  line L8 (-25, 225) -> (-25, 50)
  line L9 (-41, 180) -> (-51, 180)
  line L10 (-41, 96.1211) -> (-41, 180)
  line L11 (-51, 96.1211) -> (-41, 96.1211)
  line L12 (-51, 180) -> (-51, 96.1211)
  line L13 (-25, 170.1585) -> (-35.0171, 170.1585)
  line L14 (-25, 106) -> (-35, 106)
  circle C1 centre (0, 70.6) radius 13.1
  point P16 (-25, 170.1585)
  point P18 (-25, 106)
  horizontal L5
  vertical L6
  horizontal L7
  vertical L8
  horizontal L9
  vertical L10
  horizontal L11
  vertical L12
  coincident L8 P16
  perpendicular L8 L13
  coincident L8 P18
  perpendicular L8 L14
extrude "Extrude11" new body of existing geometry blind -9 named "d713_1" bodies "Cutter_LU_Wall_Cap_"
extrude "Extrude12" new body of existing geometry blind -9 named "d719_1" bodies "Cutter_LL_Wall_Cap"
sketch "Sketch11" plane through (-13.1975, 0, 0) normal (1, 0, 0) x axis (0, -1, 0)
  line L1 (-52.3693, -255.1758) -> (-52.3693, -30.245)
  line L2 (-32.3693, -30.245) -> (-2.1894, -30.245)
  curve K1 (36.0257, -253.4503) -> (39.9781, -236.096)
  line L3 (36.0257, -253.4503) -> (3.2602, -255.1758)
  line L4 (-1.9988, -255.1758) -> (-52.3693, -255.1758)
  line L5 (-52.3693, -30.245) -> (-32.3693, -30.245)
  arc A1 centre (-2.1894, -80.245) radius 50 clockwise from (-2.1894, -30.245) to (40.2825, -106.6295)
  arc A2 centre (82.7543, -133.0139) radius 50 clockwise from (32.7706, -134.2915) to (40.2825, -106.6295)
  arc A3 centre (2.3992, -135.0677) radius 30.3814 clockwise from (32.7706, -134.2915) to (32.4457, -139.5658)
  arc A4 centre (81.8947, -146.9684) radius 50 clockwise from (41.2627, -176.1067) to (32.4457, -139.5658)
  arc A5 centre (0.6307, -205.245) radius 50 clockwise from (3.2602, -255.1758) to (-1.9988, -255.1758)
  arc A6 centre (0.6307, -205.245) radius 50 clockwise from (41.2627, -176.1067) to (39.9781, -236.096)
remove_body "RemoveBody1"
sketch "Sketch12" plane through (-18, 0, 0) normal (-1, 0, 0) x axis (0, -1, 0)
  circle C1 centre (-0.0736, 205.414) radius 13.1
extrude "Extrude13" new body of existing geometry blind -11 bodies "LeftUpperCutter"
sketch "Sketch3" plane through (-17, 0, 0) normal (1, 0, 0) x axis (0, 1, 0)
  line L1 (33, 28) -> (2.8201, 28)
  line L2 (53, 28) -> (33, 28)
  line L3 (53, 253.2053) -> (53, 28)
  line L4 (-35.395, 253.2053) -> (53, 253.2053)
  curve K1 (-35.395, 253.2053) -> (-39.3474, 235.851)
  line L5 (13.4103, 132.8522) -> (13.4103, 142.8522)
  line L6 (-11.9897, 142.8522) -> (-11.9897, 132.8522)
  line L7 (35, 213) -> (35, 194)
  line L8 (42, 213) -> (35, 213)
  line L9 (42, 194) -> (42, 213)
  line L10 (35, 194) -> (42, 194)
  arc A1 centre (2.8201, 80) radius 52 clockwise from (2.8201, 28) to (-40.4895, 108.7798)
  arc A2 centre (0, 205) radius 50 clockwise from (-40.632, 175.8617) to (-39.3474, 235.851)
  arc A3 centre (-81.264, 146.7234) radius 50 clockwise from (-40.632, 175.8617) to (-31.815, 139.3208)
  arc A4 centre (-1.7685, 134.8228) radius 30.3814 clockwise from (-32.1436, 135.4388) to (-31.815, 139.3208)
  arc A5 centre (-82.1333, 136.4527) radius 50 clockwise from (-32.1436, 135.4388) to (-40.4895, 108.7798)
  circle C1 centre (51, 205) radius 1.5
  circle C2 centre (0.6307, 70.355) radius 13.1
  arc A6 centre (0.7103, 132.8522) radius 12.7 clockwise from (13.4103, 132.8522) to (-11.9897, 132.8522)
  arc A7 centre (0.7103, 142.8522) radius 12.7 clockwise from (-11.9897, 142.8522) to (13.4103, 142.8522)
  circle C3 centre (0.7043, 205.169) radius 13.1
  circle C4 centre (-38.4779, 86.3786) radius 7
  circle C5 centre (-38.4779, 196.3786) radius 7
  circle C6 centre (0.7043, 205.169) radius 13.5
  concentric C3 C6
  dimension "d1392" diameter C6 = 27
extrude "Extrude4" cut sketch "Sketch3" profile of C3 along normal blind 6.2
extrude "Extrude5" add of existing geometry blind 0.8
extrude "Extrude6" add of existing geometry blind 1.8
extrude "Extrude7" add of existing geometry to an object
move "Move13"
combine "Combine3"
sketch "Sketch5" plane through (132, 0, 0) normal (1, 0, 0) x axis (0, 1, 0)
  curve K1 (-41.7381, 92.8101) -> (-42.0981, 81.8831)
  curve K2 (-35.4016, 81.8831) -> (-35.7616, 92.8101)
  curve K3 (-41.7381, 202.8101) -> (-42.0981, 191.8831)
  curve K4 (-35.4016, 191.8831) -> (-35.7616, 202.8101)
  line L1 (-24.3693, 220.155) -> (-24.3693, 190.155)
  line L2 (15.6307, 230.155) -> (-14.3693, 230.155)
  line L3 (25.6307, 190.155) -> (25.6307, 220.155)
  line L4 (-14.3693, 180.155) -> (15.6307, 180.155)
  line L5 (-18, 145) -> (-18, 127)
  line L6 (33, 153) -> (-10, 153)
  line L7 (41, 127) -> (41, 145)
  line L8 (-10, 119) -> (33, 119)
  line L9 (33, 28) -> (2.8201, 28)
  line L10 (53, 28) -> (33, 28)
  line L11 (53, 253.2053) -> (53, 28)
  line L12 (-35.395, 253.2053) -> (53, 253.2053)
  curve K5 (-35.395, 253.2053) -> (-39.3474, 235.851)
  line L13 (30.5572, 235.3986) -> (-29.092, 235.3986)
  line L14 (30.5572, 175.1248) -> (30.5572, 235.3986)
  line L15 (-29.092, 175.1248) -> (30.5572, 175.1248)
  line L16 (-29.092, 235.3986) -> (-29.092, 175.1248)
  arc A1 centre (-38.7498, 86.5785) radius 6.911 clockwise from (-41.7381, 92.8101) to (-35.7616, 92.8101)
  arc A2 centre (-38.7498, 86.5785) radius 5.767 clockwise from (-35.4016, 81.8831) to (-42.0981, 81.8831)
  arc A3 centre (-38.7498, 196.5785) radius 6.911 clockwise from (-41.7381, 202.8101) to (-35.7616, 202.8101)
  arc A4 centre (-38.7498, 196.5785) radius 5.767 clockwise from (-35.4016, 191.8831) to (-42.0981, 191.8831)
  circle C1 centre (28.1307, 205.155) radius 1.65
  circle C2 centre (0.6307, 177.655) radius 1.65
  circle C3 centre (-26.8693, 205.155) radius 1.65
  circle C4 centre (0.6307, 232.655) radius 1.65
  circle C5 centre (39.9595, 118.7954) radius 1.4
  circle C6 centre (39.9595, 153.2046) radius 1.4
  circle C7 centre (-16.9412, 117.9586) radius 1.4
  circle C8 centre (-17.953, 152.353) radius 1.4
  arc A5 centre (-14.3693, 220.155) radius 10 clockwise from (-24.3693, 220.155) to (-14.3693, 230.155)
  arc A6 centre (15.6307, 220.155) radius 10 clockwise from (15.6307, 230.155) to (25.6307, 220.155)
  arc A7 centre (15.6307, 190.155) radius 10 clockwise from (25.6307, 190.155) to (15.6307, 180.155)
  arc A8 centre (-14.3693, 190.155) radius 10 clockwise from (-14.3693, 180.155) to (-24.3693, 190.155)
  arc A9 centre (-10, 127) radius 8 clockwise from (-10, 119) to (-18, 127)
  arc A10 centre (-10, 145) radius 8 clockwise from (-18, 145) to (-10, 153)
  arc A11 centre (33, 145) radius 8 clockwise from (33, 153) to (41, 145)
  arc A12 centre (33, 127) radius 8 clockwise from (41, 127) to (33, 119)
  arc A13 centre (0, 205) radius 50 clockwise from (-40.632, 175.8617) to (-39.3474, 235.851)
  arc A14 centre (-81.264, 146.7234) radius 50 clockwise from (-40.632, 175.8617) to (-31.815, 139.3208)
  arc A15 centre (-1.7685, 134.8228) radius 30.3814 clockwise from (-32.1436, 135.4388) to (-31.815, 139.3208)
  arc A16 centre (-82.1333, 136.4527) radius 50 clockwise from (-32.1436, 135.4388) to (-40.4895, 108.7798)
  arc A17 centre (2.8201, 80) radius 52 clockwise from (2.8201, 28) to (-40.4895, 108.7798)
  circle C9 centre (0.6307, 70.355) radius 32.5
  horizontal L13
  vertical L14
  horizontal L15
  vertical L16
extrude "Extrude14" add sketch "Sketch5" profile of C1 C2 C3 C4 L1 A5 L2 A6 L3 A7 L4 A8 L13 L14 L15 L16 against normal blind 7
position "Position35"
combine "Combine13"
extrude "Extrude15" cut of existing geometry blind -0.4
move "Move15"
position "Position36"
extrude "Extrude16" cut of existing geometry to an object
remove_body "RemoveBody1"
remove_body "RemoveBody2"
remove_body "RemoveBody3"
remove_body "RemoveBody4"
extrude "Extrude17" cut of existing geometry to an object bodies "Right_wall_Final (1)"
remove_body "RemoveBody5"
sketch "Sketch6" plane through (132, 0, 0) normal (1, 0, 0) x axis (0, 1, 0)
  line L1 (-24.6413, 218.3549) -> (-24.6413, 188.3549)
  line L2 (15.3587, 228.3549) -> (-14.6413, 228.3549)
  line L3 (25.3587, 188.3549) -> (25.3587, 218.3549)
  line L4 (-14.6413, 178.3549) -> (15.3587, 178.3549)
  curve K1 (-41.7381, 92.8101) -> (-42.0981, 81.8831)
  curve K2 (-35.4016, 81.8831) -> (-35.7616, 92.8101)
  curve K3 (-41.7381, 202.8101) -> (-42.0981, 191.8831)
  curve K4 (-35.4016, 191.8831) -> (-35.7616, 202.8101)
  line L5 (-18, 145) -> (-18, 127)
  line L6 (33, 153) -> (-10, 153)
  line L7 (41, 127) -> (41, 145)
  line L8 (-10, 119) -> (33, 119)
  line L9 (33, 28) -> (2.8201, 28)
  line L10 (53, 28) -> (33, 28)
  line L11 (53, 253.2053) -> (53, 28)
  line L12 (-35.395, 253.2053) -> (53, 253.2053)
  curve K5 (-35.395, 253.2053) -> (-39.3474, 235.851)
  arc A1 centre (-14.6413, 218.3549) radius 10 clockwise from (-24.6413, 218.3549) to (-14.6413, 228.3549)
  arc A2 centre (15.3587, 218.3549) radius 10 clockwise from (15.3587, 228.3549) to (25.3587, 218.3549)
  arc A3 centre (15.3587, 188.3549) radius 10 clockwise from (25.3587, 188.3549) to (15.3587, 178.3549)
  arc A4 centre (-14.6413, 188.3549) radius 10 clockwise from (-14.6413, 178.3549) to (-24.6413, 188.3549)
  arc A5 centre (-38.7498, 86.5785) radius 6.911 clockwise from (-41.7381, 92.8101) to (-35.7616, 92.8101)
  arc A6 centre (-38.7498, 86.5785) radius 5.767 clockwise from (-35.4016, 81.8831) to (-42.0981, 81.8831)
  arc A7 centre (-38.7498, 196.5785) radius 6.911 clockwise from (-41.7381, 202.8101) to (-35.7616, 202.8101)
  arc A8 centre (-38.7498, 196.5785) radius 5.767 clockwise from (-35.4016, 191.8831) to (-42.0981, 191.8831)
  circle C1 centre (39.9595, 118.7954) radius 1.4
  circle C2 centre (39.9595, 153.2046) radius 1.4
  circle C3 centre (-16.9412, 117.9586) radius 1.4
  circle C4 centre (-17.953, 152.353) radius 1.4
  arc A9 centre (-10, 127) radius 8 clockwise from (-10, 119) to (-18, 127)
  arc A10 centre (-10, 145) radius 8 clockwise from (-18, 145) to (-10, 153)
  arc A11 centre (33, 145) radius 8 clockwise from (33, 153) to (41, 145)
  arc A12 centre (33, 127) radius 8 clockwise from (41, 127) to (33, 119)
  arc A13 centre (0, 205) radius 50 clockwise from (-40.632, 175.8617) to (-39.3474, 235.851)
  arc A14 centre (-81.264, 146.7234) radius 50 clockwise from (-40.632, 175.8617) to (-31.815, 139.3208)
  arc A15 centre (-1.7685, 134.8228) radius 30.3814 clockwise from (-32.1436, 135.4388) to (-31.815, 139.3208)
  arc A16 centre (-82.1333, 136.4527) radius 50 clockwise from (-32.1436, 135.4388) to (-40.4895, 108.7798)
  arc A17 centre (2.8201, 80) radius 52 clockwise from (2.8201, 28) to (-40.4895, 108.7798)
  circle C5 centre (0.6307, 70.355) radius 32.5
  circle C6 centre (0.6307, 70.355) radius 32.5
  concentric C5 C6
  dimension "d1416" diameter C6 = 65
extrude "Extrude18" add sketch "Sketch6" profile of C5 C6 to an object
remove_body "RemoveBody10"
remove_body "RemoveBody11"
remove_body "RemoveBody12"
remove_body "RemoveBody13"
remove_body "RemoveBody14"
remove_body "RemoveBody15"
remove_body "RemoveBody16"
remove_body "RemoveBody17"
remove_body "RemoveBody18"
remove_body "RemoveBody19"
remove_body "RemoveBody20"
sketch "Sketch1" plane through (129, 0, 0) normal (-1, 0, 0) x axis (0, -1, 0)
  circle C1 centre (0, 196) radius 4.1
  circle C2 centre (0, 196) radius 13
  circle C3 centre (0, 196) radius 6.5
  circle C4 centre (0, 196) radius 32.5
  circle C5 centre (0, 196) radius 11.1
  concentric C1 C2
  concentric C2 C3
  concentric C2 C4
  concentric C3 C5
  dimension "d1419" diameter C2 = 26
  dimension "d1420" diameter C3 = 13
  dimension "d1421" diameter C4 = 65
  dimension "d1422" diameter C5 = 22.2
extrude "Extrude1" new body sketch "Sketch1" profile of C2 C5 against normal blind 7 bodies "Bearing_Cap"
extrude "Extrude2" new body sketch "Sketch1" profile of C2 C3 C5 blind -1 from offset -7
extrude "Extrude3" new body sketch "Sketch1" profile of C1 C2 C3 C5 blind -1 from offset -8
combine "Combine1"
extrude "Extrude4" new body sketch "Sketch1" profile of C2 C4 to an object
extrude "Extrude5" add sketch "Sketch1" profile of C2 C4 against normal blind 9
extrude "Extrude6" add of existing geometry blind 15
fillet "Fillet1" radius 8
thread "Thread1" ThreadOffset 0 ThreadLength 10
sketch "Sketch2" plane through (153, 0, 0) normal (1, 0, 0) x axis (0, 1, 0)
  circle C1 centre (0, 196) radius 24.3513
extrude "Extrude7" new body sketch "Sketch1" along normal blind 2 and against normal blind 10 bodies "Bearing_Cap_Cutter"
thread "Thread2" ThreadOffset 0 ThreadLength 10
combine "Combine14"
offset_faces "OffsetFaces1" distance -0.3
sketch "Sketch7" plane through (132, 0, 0) normal (1, 0, 0) x axis (0, 1, 0)
  curve K1 (30.3781, 72.1723) -> (-16.7801, 97.9933)
  curve K2 (-31.7648, 74.3864) -> (11.6713, 42.7017)
  line L1 (-24.6413, 218.3549) -> (-24.6413, 188.3549)
  line L2 (15.3587, 228.3549) -> (-14.6413, 228.3549)
  line L3 (25.3587, 188.3549) -> (25.3587, 218.3549)
  line L4 (-14.6413, 178.3549) -> (15.3587, 178.3549)
  curve K3 (-41.7381, 92.8101) -> (-42.0981, 81.8831)
  curve K4 (-35.4016, 81.8831) -> (-35.7616, 92.8101)
  curve K5 (-41.7381, 202.8101) -> (-42.0981, 191.8831)
  curve K6 (-35.4016, 191.8831) -> (-35.7616, 202.8101)
  line L5 (-18, 145) -> (-18, 127)
  line L6 (33, 153) -> (-10, 153)
  line L7 (41, 127) -> (41, 145)
  line L8 (-10, 119) -> (33, 119)
  line L9 (33, 28) -> (2.8201, 28)
  line L10 (53, 28) -> (33, 28)
  line L11 (53, 253.2053) -> (53, 28)
  line L12 (-35.395, 253.2053) -> (53, 253.2053)
  curve K7 (-35.395, 253.2053) -> (-39.3474, 235.851)
  line L13 (15.3587, 233.3549) -> (-14.6413, 233.3549)
  line L14 (30.3587, 188.3549) -> (30.3587, 218.3549)
  line L15 (-14.6413, 173.3549) -> (15.3587, 173.3549)
  line L16 (-29.6413, 218.3549) -> (-29.6413, 188.3549)
  arc A1 centre (0.3587, 70.5549) radius 30.0629 clockwise from (30.3781, 72.1723) to (11.6713, 42.7017)
  arc A2 centre (0.3587, 70.5549) radius 32.3513 clockwise from (-31.7648, 74.3864) to (-16.7801, 97.9933)
  arc A3 centre (-14.6413, 218.3549) radius 10 clockwise from (-24.6413, 218.3549) to (-14.6413, 228.3549)
  arc A4 centre (15.3587, 218.3549) radius 10 clockwise from (15.3587, 228.3549) to (25.3587, 218.3549)
  arc A5 centre (15.3587, 188.3549) radius 10 clockwise from (25.3587, 188.3549) to (15.3587, 178.3549)
  arc A6 centre (-14.6413, 188.3549) radius 10 clockwise from (-14.6413, 178.3549) to (-24.6413, 188.3549)
  arc A7 centre (-38.7498, 86.5785) radius 6.911 clockwise from (-41.7381, 92.8101) to (-35.7616, 92.8101)
  arc A8 centre (-38.7498, 86.5785) radius 5.767 clockwise from (-35.4016, 81.8831) to (-42.0981, 81.8831)
  arc A9 centre (-38.7498, 196.5785) radius 6.911 clockwise from (-41.7381, 202.8101) to (-35.7616, 202.8101)
  arc A10 centre (-38.7498, 196.5785) radius 5.767 clockwise from (-35.4016, 191.8831) to (-42.0981, 191.8831)
  circle C1 centre (39.9595, 118.7954) radius 1.4
  circle C2 centre (39.9595, 153.2046) radius 1.4
  circle C3 centre (-16.9412, 117.9586) radius 1.4
  circle C4 centre (-17.953, 152.353) radius 1.4
  arc A11 centre (-10, 127) radius 8 clockwise from (-10, 119) to (-18, 127)
  arc A12 centre (-10, 145) radius 8 clockwise from (-18, 145) to (-10, 153)
  arc A13 centre (33, 145) radius 8 clockwise from (33, 153) to (41, 145)
  arc A14 centre (33, 127) radius 8 clockwise from (41, 127) to (33, 119)
  arc A15 centre (0, 205) radius 50 clockwise from (-40.632, 175.8617) to (-39.3474, 235.851)
  arc A16 centre (-81.264, 146.7234) radius 50 clockwise from (-40.632, 175.8617) to (-31.815, 139.3208)
  arc A17 centre (-1.7685, 134.8228) radius 30.3814 clockwise from (-32.1436, 135.4388) to (-31.815, 139.3208)
  arc A18 centre (-82.1333, 136.4527) radius 50 clockwise from (-32.1436, 135.4388) to (-40.4895, 108.7798)
  arc A19 centre (2.8201, 80) radius 52 clockwise from (2.8201, 28) to (-40.4895, 108.7798)
  arc A20 centre (-14.6413, 218.3549) radius 15 clockwise from (-29.6413, 218.3549) to (-14.6413, 233.3549)
  arc A21 centre (15.3587, 218.3549) radius 15 clockwise from (15.3587, 233.3549) to (30.3587, 218.3549)
  arc A22 centre (15.3587, 188.3549) radius 15 clockwise from (30.3587, 188.3549) to (15.3587, 173.3549)
  arc A23 centre (-14.6413, 188.3549) radius 15 clockwise from (-14.6413, 173.3549) to (-29.6413, 188.3549)
  circle C5 centre (0.3587, 230.8549) radius 1
  circle C6 centre (0.3587, 175.8549) radius 1
  circle C7 centre (-27.1413, 203.3549) radius 1
  circle C8 centre (27.8587, 203.3549) radius 1
extrude "Extrude19" cut sketch "Sketch7" profile of C5 C6 C7 C8 against normal blind 4
offset_faces "OffsetFaces2" distance -2
offset_faces "OffsetFaces3" distance -4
